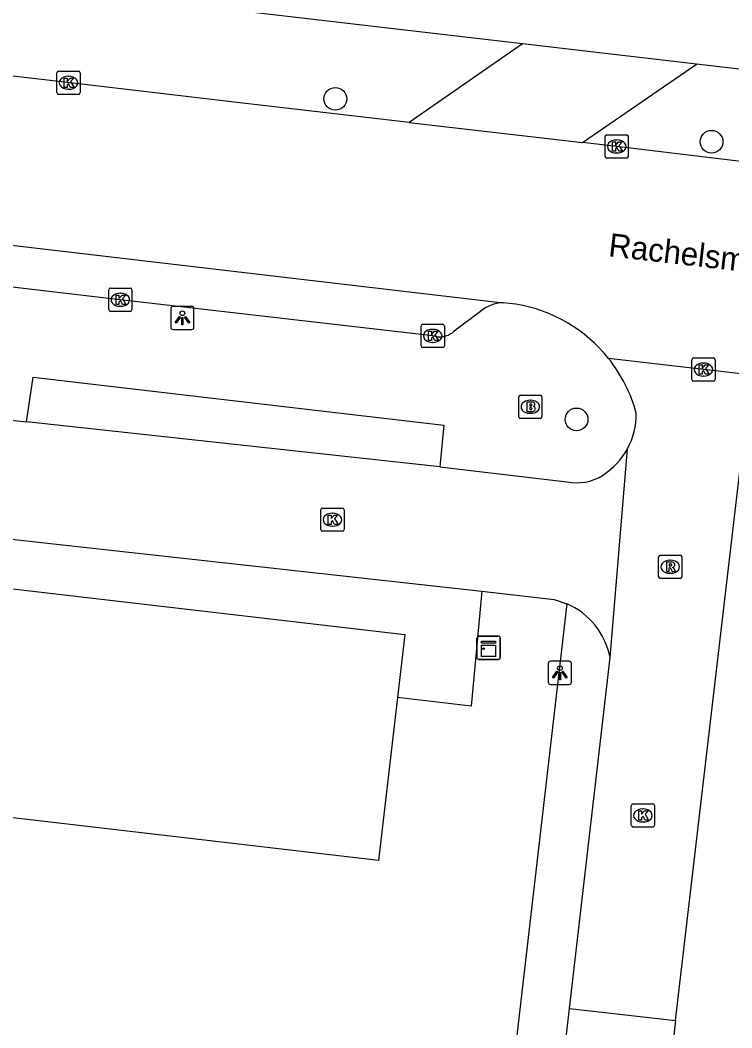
# Model space of a CAD drawing. Extents: x 161243 to 161752, y 384138 to 384885.
# Drawn here: x 161369.07 to 161399.7, y 384622.09 to 384665.48 of the extents above; entities that cross this region are included whole.
import ezdxf

# ---------------------------------------------------------------- set-up
doc = ezdxf.new("R2010")
doc.units = 0
for name, color, linetype in [('IMGEO_Boom', 7, 'Continuous'), ('IMGEO_Brandkraan', 7, 'Continuous'), ('IMGEO_Kast', 7, 'Continuous'), ('IMGEO_Kolk', 7, 'Continuous'), ('IMGEO_Lichtpunt', 7, 'Continuous'), ('IMGEO_Openbare_ruimte_label', 7, 'Continuous'), ('IMGEO_Pand', 7, 'Continuous'), ('IMGEO_Parkeervlak_open', 7, 'Continuous'), ('IMGEO_Rijbaan_lokaal_gesloten', 7, 'Continuous'), ('IMGEO_Rijbaan_lokaal_open', 7, 'Continuous'), ('IMGEO_Rioolput', 7, 'Continuous'), ('IMGEO_Voetpad_open', 7, 'Continuous')]:
    doc.layers.add(name, color=color, linetype=linetype)

msp = doc.modelspace()

# ---------------------------------------------------------------- linework, layer by layer
at = {"layer": 'IMGEO_Boom'}
for centre in [(161382.634, 384662.092), (161398.831, 384660.245), (161393.019, 384648.288)]:
    msp.add_circle(centre, 0.489, dxfattribs=at)
at = {"layer": 'IMGEO_Brandkraan'}
for p, q in [((161390.528, 384648.404), (161390.528, 384649.256)), ((161390.603, 384649.33), (161391.455, 384649.33)), ((161391.529, 384649.256), (161391.529, 384648.404)), ((161391.016, 384649.11), (161391.041, 384649.11)), ((161391.455, 384648.33), (161390.603, 384648.33)), ((161391.039, 384648.55), (161391.014, 384648.55))]:
    msp.add_line(p, q, dxfattribs=at)
for points in [[(161390.528, 384648.404), (161390.528, 384649.256)], [(161390.603, 384649.33), (161391.455, 384649.33)], [(161391.529, 384649.256), (161391.529, 384648.404)], [(161390.876, 384649.03), (161390.876, 384648.63), (161391.089, 384648.63)], [(161391.107, 384649.03), (161390.876, 384649.03)], [(161391.055, 384648.949), (161391.001, 384648.949), (161391.001, 384648.873)], [(161391.001, 384648.873), (161391.054, 384648.873)], [(161391.063, 384648.797), (161391.001, 384648.797), (161391.001, 384648.716)], [(161391.001, 384648.716), (161391.063, 384648.716)], [(161391.455, 384648.33), (161390.603, 384648.33)]]:
    msp.add_lwpolyline(points, dxfattribs=at)
for centre, radius, start, end in [((161390.605, 384649.254), 0.0765, 91.552, 178.448), ((161390.605, 384649.254), 0.0765, 91.552, 178.448), ((161391.453, 384649.254), 0.0765, 1.552, 88.448), ((161391.453, 384649.254), 0.0765, 1.552, 88.448), ((161391.056, 384648.911), 0.0379, 267.8285, 90.9355), ((161391.064, 384648.756), 0.0404, 269.8759, 90.5077), ((161391.111, 384648.885), 0.145, 59.4692, 91.5367), ((161391.136, 384648.932), 0.0922, 285.5137, 58.1501), ((161391.141, 384648.74), 0.105, 301.3115, 78.989), ((161390.605, 384648.406), 0.0765, 181.552, 268.448), ((161390.605, 384648.406), 0.0765, 181.552, 268.448), ((161391.095, 384648.881), 0.251, 268.6676, 293.5347), ((161391.453, 384648.406), 0.0765, 271.552, 358.448), ((161391.453, 384648.406), 0.0765, 271.552, 358.448)]:
    msp.add_arc(centre, radius, start, end, dxfattribs=at)
for centre, major_axis, ratio, start_param, end_param in [((161391.015, 384648.83), (-0.387, 0.002), 0.722429, 4.712389, 7.853982), ((161391.04, 384648.83), (-0.39, 0.002), 0.717154, 1.570796, 4.712389)]:
    msp.add_ellipse(centre, major_axis=major_axis, ratio=ratio, start_param=start_param, end_param=end_param, dxfattribs=at)
at = {"layer": 'IMGEO_Kast'}
for p, q in [((161388.733, 384638.027), (161388.733, 384638.868)), ((161388.733, 384638.868), (161388.733, 384638.027)), ((161388.808, 384638.952), (161389.649, 384638.952)), ((161389.649, 384638.952), (161388.808, 384638.952)), ((161389.733, 384638.877), (161389.733, 384638.036)), ((161389.733, 384638.036), (161389.733, 384638.877)), ((161389.658, 384637.952), (161388.817, 384637.952)), ((161388.817, 384637.952), (161389.658, 384637.952))]:
    msp.add_line(p, q, dxfattribs=at)
for points in [[(161388.928, 384638.742), (161389.528, 384638.742), (161389.528, 384638.657), (161388.928, 384638.657), (161388.928, 384638.742)], [(161388.928, 384638.567), (161389.528, 384638.567), (161389.528, 384638.078), (161388.928, 384638.078), (161388.928, 384638.567)]]:
    msp.add_lwpolyline(points, dxfattribs=at)
msp.add_circle((161389.012, 384638.416), 0.0377, dxfattribs=at)
for centre, start, end in [((161388.811, 384638.874), 92.4484, 184.2845), ((161388.811, 384638.874), 92.4484, 184.2845), ((161389.655, 384638.874), 2.4484, 94.2845), ((161389.655, 384638.874), 2.4484, 94.2845), ((161388.811, 384638.03), 182.4484, 274.2845), ((161388.811, 384638.03), 182.4484, 274.2845), ((161389.655, 384638.03), 272.4484, 4.2845), ((161389.655, 384638.03), 272.4484, 4.2845)]:
    msp.add_arc(centre, 0.0779, start, end, dxfattribs=at)
at = {"layer": 'IMGEO_Kolk'}
for p, q in [((161370.645, 384662.36), (161370.645, 384663.212)), ((161370.72, 384663.286), (161371.572, 384663.286)), ((161371.133, 384663.066), (161371.158, 384663.066)), ((161371.646, 384663.212), (161371.646, 384662.36)), ((161371.572, 384662.286), (161370.72, 384662.286)), ((161371.156, 384662.506), (161371.131, 384662.506)), ((161394.247, 384659.614), (161394.247, 384660.466)), ((161394.322, 384660.54), (161395.174, 384660.54)), ((161395.248, 384660.466), (161395.248, 384659.614)), ((161394.735, 384660.32), (161394.76, 384660.32)), ((161395.174, 384659.54), (161394.322, 384659.54)), ((161394.758, 384659.76), (161394.733, 384659.76)), ((161372.952, 384653.94), (161373.804, 384653.94)), ((161372.877, 384653.014), (161372.877, 384653.866)), ((161373.365, 384653.72), (161373.39, 384653.72)), ((161373.878, 384653.866), (161373.878, 384653.014)), ((161373.388, 384653.16), (161373.363, 384653.16)), ((161373.804, 384652.94), (161372.952, 384652.94)), ((161386.327, 384651.457), (161386.327, 384652.309)), ((161386.402, 384652.383), (161387.254, 384652.383)), ((161386.815, 384652.163), (161386.84, 384652.163)), ((161387.328, 384652.309), (161387.328, 384651.457)), ((161387.254, 384651.383), (161386.402, 384651.383)), ((161386.838, 384651.603), (161386.813, 384651.603)), ((161397.983, 384650.007), (161397.983, 384650.859)), ((161398.058, 384650.933), (161398.91, 384650.933)), ((161398.984, 384650.859), (161398.984, 384650.007)), ((161398.471, 384650.713), (161398.496, 384650.713)), ((161398.494, 384650.153), (161398.469, 384650.153)), ((161398.91, 384649.933), (161398.058, 384649.933)), ((161382.008, 384643.542), (161382.008, 384644.394)), ((161382.083, 384644.468), (161382.935, 384644.468)), ((161383.009, 384644.394), (161383.009, 384643.542)), ((161382.496, 384644.248), (161382.521, 384644.248)), ((161382.519, 384643.688), (161382.494, 384643.688)), ((161382.935, 384643.468), (161382.083, 384643.468)), ((161395.377, 384630.808), (161395.377, 384631.66)), ((161395.452, 384631.734), (161396.304, 384631.734)), ((161395.865, 384631.514), (161395.89, 384631.514)), ((161396.378, 384631.66), (161396.378, 384630.808)), ((161395.888, 384630.954), (161395.863, 384630.954)), ((161396.304, 384630.734), (161395.452, 384630.734))]:
    msp.add_line(p, q, dxfattribs=at)
for points in [[(161370.645, 384662.36), (161370.645, 384663.212)], [(161370.72, 384663.286), (161371.572, 384663.286)], [(161371.646, 384663.212), (161371.646, 384662.36)], [(161370.966, 384662.986), (161371.089, 384662.986), (161371.089, 384662.835), (161371.219, 384662.986), (161371.383, 384662.986), (161371.237, 384662.835), (161371.39, 384662.586), (161371.238, 384662.586), (161371.153, 384662.75), (161371.089, 384662.683), (161371.089, 384662.586), (161370.966, 384662.586), (161370.966, 384662.986)], [(161371.572, 384662.286), (161370.72, 384662.286)], [(161394.247, 384659.614), (161394.247, 384660.466)], [(161394.322, 384660.54), (161395.174, 384660.54)], [(161395.248, 384660.466), (161395.248, 384659.614)], [(161394.568, 384660.24), (161394.691, 384660.24), (161394.691, 384660.089), (161394.821, 384660.24), (161394.985, 384660.24), (161394.839, 384660.089), (161394.992, 384659.84), (161394.84, 384659.84), (161394.755, 384660.004), (161394.691, 384659.937), (161394.691, 384659.84), (161394.568, 384659.84), (161394.568, 384660.24)], [(161395.174, 384659.54), (161394.322, 384659.54)], [(161372.952, 384653.94), (161373.804, 384653.94)], [(161372.877, 384653.014), (161372.877, 384653.866)], [(161373.198, 384653.64), (161373.321, 384653.64), (161373.321, 384653.489), (161373.451, 384653.64), (161373.615, 384653.64), (161373.469, 384653.489), (161373.622, 384653.24), (161373.47, 384653.24), (161373.385, 384653.404), (161373.321, 384653.337), (161373.321, 384653.24), (161373.198, 384653.24), (161373.198, 384653.64)], [(161373.878, 384653.866), (161373.878, 384653.014)], [(161373.804, 384652.94), (161372.952, 384652.94)], [(161386.327, 384651.457), (161386.327, 384652.309)], [(161386.402, 384652.383), (161387.254, 384652.383)], [(161387.328, 384652.309), (161387.328, 384651.457)], [(161386.648, 384652.083), (161386.771, 384652.083), (161386.771, 384651.932), (161386.901, 384652.083), (161387.065, 384652.083), (161386.919, 384651.932), (161387.072, 384651.683), (161386.92, 384651.683), (161386.835, 384651.847), (161386.771, 384651.78), (161386.771, 384651.683), (161386.648, 384651.683), (161386.648, 384652.083)], [(161387.254, 384651.383), (161386.402, 384651.383)], [(161397.983, 384650.007), (161397.983, 384650.859)], [(161398.058, 384650.933), (161398.91, 384650.933)], [(161398.984, 384650.859), (161398.984, 384650.007)], [(161398.304, 384650.633), (161398.427, 384650.633), (161398.427, 384650.482), (161398.557, 384650.633), (161398.721, 384650.633), (161398.575, 384650.482), (161398.728, 384650.233), (161398.576, 384650.233), (161398.491, 384650.397), (161398.427, 384650.33), (161398.427, 384650.233), (161398.304, 384650.233), (161398.304, 384650.633)], [(161398.91, 384649.933), (161398.058, 384649.933)], [(161382.008, 384643.542), (161382.008, 384644.394)], [(161382.083, 384644.468), (161382.935, 384644.468)], [(161383.009, 384644.394), (161383.009, 384643.542)], [(161382.329, 384644.168), (161382.452, 384644.168), (161382.452, 384644.017), (161382.582, 384644.168), (161382.746, 384644.168), (161382.6, 384644.017), (161382.753, 384643.768), (161382.601, 384643.768), (161382.516, 384643.932), (161382.452, 384643.865), (161382.452, 384643.768), (161382.329, 384643.768), (161382.329, 384644.168)], [(161382.935, 384643.468), (161382.083, 384643.468)], [(161395.377, 384630.808), (161395.377, 384631.66)], [(161395.452, 384631.734), (161396.304, 384631.734)], [(161395.698, 384631.434), (161395.821, 384631.434), (161395.821, 384631.283), (161395.951, 384631.434), (161396.115, 384631.434), (161395.969, 384631.283), (161396.122, 384631.034), (161395.97, 384631.034), (161395.885, 384631.198), (161395.821, 384631.131), (161395.821, 384631.034), (161395.698, 384631.034), (161395.698, 384631.434)], [(161396.378, 384631.66), (161396.378, 384630.808)], [(161396.304, 384630.734), (161395.452, 384630.734)]]:
    msp.add_lwpolyline(points, dxfattribs=at)
for centre, start, end in [((161370.722, 384663.21), 91.552, 178.448), ((161370.722, 384663.21), 91.552, 178.448), ((161371.57, 384663.21), 1.552, 88.448), ((161371.57, 384663.21), 1.552, 88.448), ((161370.722, 384662.362), 181.552, 268.448), ((161370.722, 384662.362), 181.552, 268.448), ((161371.57, 384662.362), 271.552, 358.448), ((161371.57, 384662.362), 271.552, 358.448), ((161394.324, 384660.464), 91.552, 178.448), ((161394.324, 384660.464), 91.552, 178.448), ((161395.172, 384660.464), 1.552, 88.448), ((161395.172, 384660.464), 1.552, 88.448), ((161394.324, 384659.616), 181.552, 268.448), ((161394.324, 384659.616), 181.552, 268.448), ((161395.172, 384659.616), 271.552, 358.448), ((161395.172, 384659.616), 271.552, 358.448), ((161372.954, 384653.864), 91.552, 178.448), ((161372.954, 384653.864), 91.552, 178.448), ((161373.802, 384653.864), 1.552, 88.448), ((161373.802, 384653.864), 1.552, 88.448), ((161372.954, 384653.016), 181.552, 268.448), ((161372.954, 384653.016), 181.552, 268.448), ((161373.802, 384653.016), 271.552, 358.448), ((161373.802, 384653.016), 271.552, 358.448), ((161386.404, 384652.307), 91.552, 178.448), ((161386.404, 384652.307), 91.552, 178.448), ((161387.252, 384652.307), 1.552, 88.448), ((161387.252, 384652.307), 1.552, 88.448), ((161386.404, 384651.459), 181.552, 268.448), ((161386.404, 384651.459), 181.552, 268.448), ((161387.252, 384651.459), 271.552, 358.448), ((161387.252, 384651.459), 271.552, 358.448), ((161398.06, 384650.857), 91.552, 178.448), ((161398.06, 384650.857), 91.552, 178.448), ((161398.908, 384650.857), 1.552, 88.448), ((161398.908, 384650.857), 1.552, 88.448), ((161398.06, 384650.009), 181.552, 268.448), ((161398.06, 384650.009), 181.552, 268.448), ((161398.908, 384650.009), 271.552, 358.448), ((161398.908, 384650.009), 271.552, 358.448), ((161382.085, 384644.392), 91.552, 178.448), ((161382.085, 384644.392), 91.552, 178.448), ((161382.933, 384644.392), 1.552, 88.448), ((161382.933, 384644.392), 1.552, 88.448), ((161382.085, 384643.544), 181.552, 268.448), ((161382.085, 384643.544), 181.552, 268.448), ((161382.933, 384643.544), 271.552, 358.448), ((161382.933, 384643.544), 271.552, 358.448), ((161395.454, 384631.658), 91.552, 178.448), ((161395.454, 384631.658), 91.552, 178.448), ((161396.302, 384631.658), 1.552, 88.448), ((161396.302, 384631.658), 1.552, 88.448), ((161395.454, 384630.81), 181.552, 268.448), ((161395.454, 384630.81), 181.552, 268.448), ((161396.302, 384630.81), 271.552, 358.448), ((161396.302, 384630.81), 271.552, 358.448)]:
    msp.add_arc(centre, 0.0765, start, end, dxfattribs=at)
for centre, major_axis, ratio, start_param, end_param in [((161371.132, 384662.786), (-0.387, 0.002), 0.722429, 4.712389, 7.853982), ((161371.157, 384662.786), (-0.39, 0.002), 0.717154, 1.570796, 4.712389), ((161394.734, 384660.04), (-0.387, 0.002), 0.722429, 4.712389, 7.853982), ((161394.759, 384660.04), (-0.39, 0.002), 0.717154, 1.570796, 4.712389), ((161373.364, 384653.44), (-0.387, 0.002), 0.722429, 4.712389, 7.853982), ((161373.389, 384653.44), (-0.39, 0.002), 0.717154, 1.570796, 4.712389), ((161386.814, 384651.883), (-0.387, 0.002), 0.722429, 4.712389, 7.853982), ((161386.839, 384651.883), (-0.39, 0.002), 0.717154, 1.570796, 4.712389), ((161398.47, 384650.433), (-0.387, 0.002), 0.722429, 4.712389, 7.853982), ((161398.495, 384650.433), (-0.39, 0.002), 0.717154, 1.570796, 4.712389), ((161382.495, 384643.968), (-0.387, 0.002), 0.722429, 4.712389, 7.853982), ((161382.52, 384643.968), (-0.39, 0.002), 0.717154, 1.570796, 4.712389), ((161395.864, 384631.234), (-0.387, 0.002), 0.722429, 4.712389, 7.853982), ((161395.889, 384631.234), (-0.39, 0.002), 0.717154, 1.570796, 4.712389)]:
    msp.add_ellipse(centre, major_axis=major_axis, ratio=ratio, start_param=start_param, end_param=end_param, dxfattribs=at)
at = {"layer": 'IMGEO_Lichtpunt'}
for p, q in [((161375.553, 384653.061), (161375.553, 384652.254)), ((161375.553, 384653.061), (161375.553, 384652.254)), ((161376.455, 384653.156), (161375.647, 384653.156)), ((161376.455, 384653.156), (161375.647, 384653.156)), ((161376.549, 384652.254), (161376.549, 384653.061)), ((161376.549, 384652.254), (161376.549, 384653.061)), ((161375.647, 384652.16), (161376.455, 384652.16)), ((161375.647, 384652.16), (161376.455, 384652.16)), ((161392.705, 384637.871), (161391.897, 384637.871)), ((161392.705, 384637.871), (161391.897, 384637.871)), ((161391.803, 384637.776), (161391.803, 384636.969)), ((161391.803, 384637.776), (161391.803, 384636.969)), ((161392.799, 384636.969), (161392.799, 384637.776)), ((161392.799, 384636.969), (161392.799, 384637.776)), ((161391.897, 384636.875), (161392.705, 384636.875)), ((161391.897, 384636.875), (161392.705, 384636.875))]:
    msp.add_line(p, q, dxfattribs=at)
for points in [[(161375.927, 384652.725), (161375.966, 384652.697), (161375.778, 384652.435), (161375.74, 384652.462), (161375.927, 384652.725)], [(161376.029, 384652.677), (161376.076, 384652.677), (161376.076, 384652.355), (161376.029, 384652.355), (161376.029, 384652.677)], [(161376.139, 384652.697), (161376.177, 384652.724), (161376.364, 384652.462), (161376.325, 384652.434), (161376.139, 384652.697)], [(161392.177, 384637.44), (161392.216, 384637.412), (161392.028, 384637.15), (161391.99, 384637.177), (161392.177, 384637.44)], [(161392.389, 384637.412), (161392.427, 384637.439), (161392.614, 384637.177), (161392.575, 384637.149), (161392.389, 384637.412)], [(161392.279, 384637.392), (161392.326, 384637.392), (161392.326, 384637.07), (161392.279, 384637.07), (161392.279, 384637.392)]]:
    msp.add_lwpolyline(points, dxfattribs=at)
for centre in [(161376.052, 384652.859), (161392.302, 384637.574)]:
    msp.add_circle(centre, 0.0994, dxfattribs=at)
for centre, start, end in [((161375.647, 384653.061), 90, 180), ((161375.647, 384653.061), 90, 180), ((161376.455, 384653.061), 0, 90), ((161376.455, 384653.061), 0, 90), ((161375.647, 384652.254), 180, 270), ((161375.647, 384652.254), 180, 270), ((161376.455, 384652.254), 270, 0), ((161376.455, 384652.254), 270, 360), ((161391.897, 384637.776), 90, 180), ((161391.897, 384637.776), 90, 180), ((161392.705, 384637.776), 0, 90), ((161392.705, 384637.776), 0, 90), ((161391.897, 384636.969), 180, 270), ((161391.897, 384636.969), 180, 270), ((161392.705, 384636.969), 270, 0), ((161392.705, 384636.969), 270, 360)]:
    msp.add_arc(centre, 0.0946, start, end, dxfattribs=at)
at = {"layer": 'IMGEO_Pand'}
for points in [[(161339.265, 384642.015), (161339.541, 384644.388), (161385.625, 384639.018), (161385.31, 384636.318)], [(161385.31, 384636.318), (161384.492, 384629.298), (161341.346, 384634.326), (161341.28, 384633.76), (161338.47, 384631.536), (161337.879, 384631.605), (161330.356, 384566.963), (161329.778, 384567.03), (161329.206, 384562.128)]]:
    msp.add_lwpolyline(points, dxfattribs=at)
at = {"layer": 'IMGEO_Parkeervlak_open'}
for points in [[(161386.991, 384651.842), (161386.828, 384651.884), (161373.378, 384653.44), (161350.975, 384656.07), (161350.318, 384656.437), (161349.675, 384657.343)], [(161388.883, 384652.935), (161387.754, 384652.082)], [(161369.332, 384648.189), (161369.629, 384650.1), (161387.303, 384648.045), (161387.138, 384646.243)]]:
    msp.add_lwpolyline(points, dxfattribs=at)
for centre, radius, start, end in [((161389.941, 384651.653), 1.662, 93.0057, 129.5352), ((161387.088, 384652.868), 1.03, 264.6158, 310.3059)]:
    msp.add_arc(centre, radius, start, end, dxfattribs=at)
at = {"layer": 'IMGEO_Rijbaan_lokaal_gesloten'}
for points in [[(161385.812, 384661.078), (161378.041, 384661.982), (161371.462, 384662.748), (161352.098, 384665), (161346.668, 384665.574), (161337.22, 384666.762), (161335.063, 384667.031)], [(161385.812, 384661.078), (161393.279, 384660.21)], [(161434.472, 384655.36), (161433.551, 384655.465), (161424.956, 384656.433), (161420.44, 384656.941), (161394.627, 384660.053), (161393.279, 384660.21)], [(161348.386, 384658.172), (161389.854, 384653.313)], [(161390.409, 384653.248), (161389.854, 384653.313)], [(161401.463, 384650.085), (161394.401, 384650.908)]]:
    msp.add_lwpolyline(points, dxfattribs=at)
msp.add_arc((161389.365, 384646.891), 6.442, 38.5747, 80.67, dxfattribs=at)
at = {"layer": 'IMGEO_Rijbaan_lokaal_open'}
for points in [[(161357.522, 384649.433), (161369.332, 384648.189)], [(161387.138, 384646.243), (161369.332, 384648.189)], [(161394.463, 384638.035), (161395.21, 384647.024)], [(161333.288, 384644.347), (161336.314, 384646.823), (161366.853, 384643.333), (161388.946, 384640.893)], [(161387.138, 384646.243), (161392.599, 384645.601)], [(161397.281, 384622.401), (161400.088, 384646.416)], [(161388.946, 384640.893), (161392.052, 384640.525), (161392.602, 384640.347)], [(161392.722, 384622.926), (161394.463, 384638.035)], [(161392.406, 384620.184), (161392.722, 384622.926)], [(161392.722, 384622.926), (161397.281, 384622.401)], [(161397.281, 384622.401), (161396.961, 384619.66)]]:
    msp.add_lwpolyline(points, dxfattribs=at)
for centre, radius, start, end in [((161389.322, 384646.875), 6.486, 14.9877, 38.4532), ((161392.483, 384648.507), 3.105, 331.4579, 0.8228), ((161392.478, 384648.51), 3.11, 302.1487, 331.4569), ((161393.024, 384647.638), 2.081, 258.2077, 302.1915), ((161391.355, 384637.438), 3.165, 10.8726, 66.7907)]:
    msp.add_arc(centre, radius, start, end, dxfattribs=at)
at = {"layer": 'IMGEO_Rioolput'}
for p, q in [((161396.552, 384641.514), (161396.552, 384642.366)), ((161396.627, 384642.44), (161397.479, 384642.44)), ((161397.04, 384642.22), (161397.065, 384642.22)), ((161397.553, 384642.366), (161397.553, 384641.514)), ((161397.479, 384641.44), (161396.627, 384641.44)), ((161397.063, 384641.66), (161397.038, 384641.66))]:
    msp.add_line(p, q, dxfattribs=at)
for points in [[(161396.552, 384641.514), (161396.552, 384642.366)], [(161396.627, 384642.44), (161397.479, 384642.44)], [(161397.553, 384642.366), (161397.553, 384641.514)], [(161397.141, 384642.138), (161396.889, 384642.14), (161396.889, 384641.74)], [(161396.889, 384641.74), (161397.013, 384641.74), (161397.013, 384641.902), (161397.024, 384641.902)], [(161397.067, 384642.059), (161397.013, 384642.059), (161397.013, 384641.978)], [(161397.013, 384641.978), (161397.065, 384641.978)], [(161397.071, 384641.873), (161397.142, 384641.74), (161397.282, 384641.74), (161397.217, 384641.866)], [(161397.479, 384641.44), (161396.627, 384641.44)]]:
    msp.add_lwpolyline(points, dxfattribs=at)
for centre, radius, start, end in [((161396.629, 384642.364), 0.0765, 91.552, 178.448), ((161396.629, 384642.364), 0.0765, 91.552, 178.448), ((161397.477, 384642.364), 0.0765, 1.552, 88.448), ((161397.477, 384642.364), 0.0765, 1.552, 88.448), ((161397.023, 384641.849), 0.0533, 26.0293, 88.6989), ((161397.049, 384642.167), 0.19, 274.7715, 282.9687), ((161397.073, 384641.963), 0.0964, 77.0061, 93.1865), ((161397.087, 384642.02), 0.0378, 276.6634, 79.6772), ((161397.14, 384642.028), 0.109, 350.3612, 89.416), ((161397.138, 384642.028), 0.112, 277.5842, 350.9817), ((161397.122, 384641.813), 0.108, 29.5134, 73.7905), ((161396.629, 384641.516), 0.0765, 181.552, 268.448), ((161396.629, 384641.516), 0.0765, 181.552, 268.448), ((161397.477, 384641.516), 0.0765, 271.552, 358.448), ((161397.477, 384641.516), 0.0765, 271.552, 358.448)]:
    msp.add_arc(centre, radius, start, end, dxfattribs=at)
for centre, major_axis, ratio, start_param, end_param in [((161397.039, 384641.94), (-0.387, 0.002), 0.722429, 4.712389, 7.853982), ((161397.064, 384641.94), (-0.39, 0.002), 0.717154, 1.570796, 4.712389)]:
    msp.add_ellipse(centre, major_axis=major_axis, ratio=ratio, start_param=start_param, end_param=end_param, dxfattribs=at)
at = {"layer": 'IMGEO_Voetpad_open'}
for points in [[(161390.698, 384664.458), (161377.488, 384665.995), (161376.893, 384666.064), (161373.854, 384666.414)], [(161390.698, 384664.458), (161385.812, 384661.078)], [(161398.187, 384663.587), (161390.698, 384664.458)], [(161393.279, 384660.21), (161398.187, 384663.587)], [(161492.983, 384652.558), (161398.187, 384663.587)], [(161388.946, 384640.893), (161388.478, 384635.942), (161385.31, 384636.318)], [(161392.602, 384640.347), (161389.377, 384612.476)]]:
    msp.add_lwpolyline(points, dxfattribs=at)

# ---------------------------------------------------------------- texts
at = {"layer": 'IMGEO_Openbare_ruimte_label'}
msp.add_text('Rachelsmolen', height=1, rotation=353.4509, dxfattribs=at).set_placement((161394.361, 384655.317))

doc.saveas('drawing.dxf')
